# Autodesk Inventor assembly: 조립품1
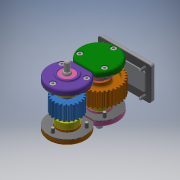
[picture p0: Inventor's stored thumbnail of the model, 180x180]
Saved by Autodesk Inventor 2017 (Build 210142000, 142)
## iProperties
Part Number: 조립품1
Material: 일반
Document SubType Name: Assembly
Designer: mrc
Mass: 1460.95 g
Surface Area: 1575.48 cm^2
Volume: 385.032 cm^3
Density: 3.79437 g/cm^3
Author: mrc
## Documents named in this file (24)
- C:\Users\mrc\Desktop\600506V1014\조립품1.iam
- C:\Users\mrc\Desktop\600506V1014\개스킷 A.ipt
- C:\Users\mrc\Desktop\600506V1014\개스킷 B.ipt
- C:\Users\mrc\Desktop\600506V1014\개스킷 C.ipt
- C:\Users\mrc\Desktop\600506V1014\베어링 6001.ipt
- 베어링 6001.ipt
- C:\Users\mrc\Desktop\600506V1014\베어링 6002.ipt
- 베어링 6002.ipt
- C:\Users\mrc\Desktop\600506V1014\본체.ipt
- C:\Users\mrc\Desktop\600506V1014\볼트 M4.ipt
- C:\Users\mrc\Desktop\600506V1014\스퍼기어 A.ipt
- C:\Users\mrc\Desktop\600506V1014\스퍼기어 B.ipt
- C:\Users\mrc\Desktop\600506V1014\오일 실 10 20 7.ipt
- C:\Users\mrc\Desktop\600506V1014\오일 실 12 22 7.ipt
- C:\Users\mrc\Desktop\600506V1014\축 A.ipt
- C:\Users\mrc\Desktop\600506V1014\축 B.ipt
- C:\Users\mrc\Desktop\600506V1014\칼라.ipt
- C:\Users\mrc\Desktop\600506V1014\커버 A.ipt
- C:\Users\mrc\Desktop\600506V1014\커버 B.ipt
- C:\Users\mrc\Desktop\600506V1014\커버 C.ipt
- C:\Users\mrc\Desktop\600506V1014\커버 D.ipt
- C:\Users\mrc\Desktop\600506V1014\커버 E.ipt
- C:\Users\mrc\Desktop\600506V1014\키 4 x 4 x 12.ipt
- C:\Users\mrc\Desktop\600506V1014\키 5 x 5 x 12.ipt
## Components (5 placed, 3 different names)
1. 개스킷 B:1
2. 개스킷 C:1
3. 개스킷 A:3
4. 개스킷 B:2
5. 개스킷 B:3
